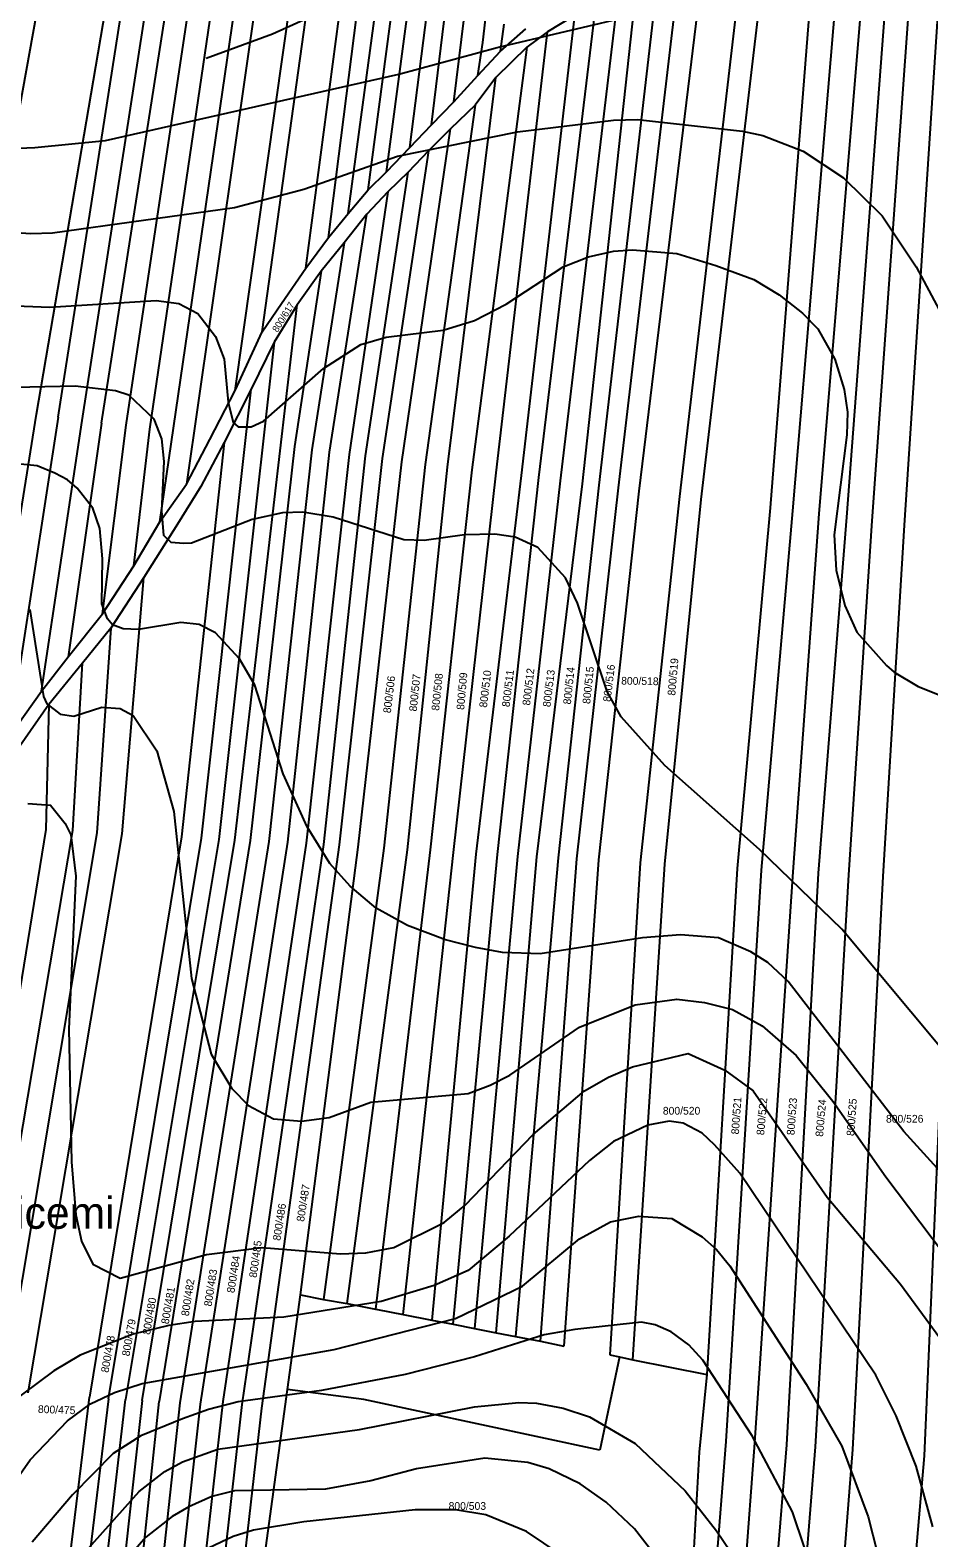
# Model space of a CAD drawing. Extents: x -555860 to -552701, y -1187050 to -1182291.
# Drawn here: x -555051.8 to -554854.6, y -1186105 to -1185774.2 of the extents above; entities that cross this region are included whole.
import ezdxf

# ---------------------------------------------------------------- set-up
doc = ezdxf.new("R2010")
doc.units = 0
for name, color, linetype in [('LEG_2b', 7, 'Continuous'), ('Level 40', 7, 'Continuous'), ('Level 41', 7, 'Continuous'), ('Level 42', 7, 'Continuous'), ('navrh_BV', 7, 'Continuous'), ('Parcelní čísla', 7, 'Continuous')]:
    doc.layers.add(name, color=color, linetype=linetype)

msp = doc.modelspace()

# ---------------------------------------------------------------- linework, layer by layer
at = {"layer": 'Level 40'}
for points in [[(-555084.64, -1185816.58), (-555051.64, -1185818.8), (-555046.92, -1185818.66), (-555006.99, -1185813.11), (-554991.74, -1185809.09), (-554971.22, -1185801.88), (-554944.87, -1185796.48), (-554923.8, -1185793.98), (-554918.53, -1185793.84), (-554895.51, -1185796.34), (-554891.07, -1185797.31), (-554882.2, -1185800.77), (-554873.32, -1185806.6), (-554864.87, -1185814.92), (-554857.38, -1185826.15), (-554846.7, -1185846.11)], [(-555052.33, -1185943.87), (-555047.34, -1185944.28), (-555044.15, -1185948.3), (-555042.9, -1185950.8), (-555041.79, -1185959.81), (-555043.32, -1185993.37), (-555042.76, -1186022.49), (-555041.79, -1186034.13), (-555040.55, -1186039.96), (-555038.05, -1186044.95), (-555032.03, -1186048.01), (-555013.09, -1186042.87), (-555000.89, -1186041.34), (-554983.7, -1186042.73), (-554978.15, -1186042.45), (-554972.05, -1186041.34), (-554960.96, -1186035.8), (-554956.38, -1186032.05), (-554941.41, -1186016.52), (-554930.18, -1186006.96), (-554924.91, -1186003.91), (-554919.64, -1186001.69), (-554907.44, -1185998.78), (-554899.39, -1186002.38), (-554893.15, -1186006.96), (-554876.93, -1186030.25), (-554860.85, -1186049.39), (-554846.56, -1186068.8)], [(-554911.18, -1186113.45), (-554919.22, -1186103.05), (-554925.46, -1186097.22), (-554931.15, -1186093.2), (-554937.94, -1186089.87), (-554942.65, -1186088.49), (-554952.08, -1186087.52), (-554967.06, -1186089.87), (-554977.04, -1186092.51), (-554987.02, -1186094.31), (-555006.99, -1186094.73), (-555011.98, -1186095.98), (-555016.97, -1186098.19), (-555020.62, -1186100.37), (-555026.4, -1186104.85), (-555064.67, -1186149.22)]]:
    msp.add_lwpolyline(points, dxfattribs=at)
at = {"layer": 'Level 41'}
for points in [[(-555184.61, -1185772.35), (-555182.67, -1185783.16), (-555181.98, -1185798.7), (-555181.14, -1185804.52), (-555179.06, -1185810.34), (-555177.8, -1185811.75), (-555176.84, -1185812.28), (-555175.04, -1185812.56), (-555173.1, -1185812.49), (-555167.28, -1185811.45), (-555148.84, -1185803.27), (-555142.16, -1185801.11), (-555134.56, -1185798.97), (-555125.68, -1185797.72), (-555110.71, -1185797.03), (-555099.61, -1185797.58), (-555084.08, -1185799.53), (-555061.34, -1185800.36), (-555050.81, -1185799.94), (-555035.28, -1185798.42), (-554970.94, -1185783.86), (-554949.31, -1185778.03), (-554902.72, -1185766.94)], [(-555104.05, -1185832.8), (-555047.48, -1185835.02), (-555024.18, -1185833.5), (-555019.19, -1185834.19), (-555015.03, -1185836.41), (-555011.15, -1185841.4), (-555009.21, -1185846.39), (-555008.38, -1185855.82), (-555007.27, -1185860.26), (-555006.16, -1185861.23), (-555003.33, -1185861.25), (-555000.61, -1185859.98), (-554987.44, -1185848.47), (-554979.26, -1185843.2), (-554973.71, -1185841.54), (-554961.23, -1185840.01), (-554954.3, -1185837.94), (-554947.37, -1185834.33), (-554934.89, -1185826.15), (-554929.34, -1185823.93), (-554923.8, -1185822.68), (-554919.64, -1185822.41), (-554909.93, -1185823.24), (-554901.4, -1185825.86), (-554893.02, -1185828.92), (-554887.47, -1185832.25), (-554882.34, -1185836.27), (-554879.01, -1185839.74), (-554875.27, -1185846.39), (-554873.19, -1185853.05), (-554872.49, -1185858.04), (-554872.63, -1185863.03), (-554875.41, -1185884.94), (-554874.99, -1185892.7), (-554873.05, -1185900.47), (-554870.41, -1185906.29), (-554863.9, -1185913.64), (-554862.27, -1185915.1), (-554856.96, -1185918.22), (-554851.97, -1185920.16)], [(-554850.86, -1185998.92), (-554873.74, -1185971.46), (-554891.77, -1185953.99), (-554912.57, -1185935.55), (-554922.13, -1185924.87), (-554925.18, -1185919.33), (-554931.7, -1185899.91), (-554934.33, -1185894.37), (-554940.44, -1185887.71), (-554945.43, -1185885.49), (-554949.86, -1185884.8), (-554956.52, -1185884.94), (-554965.39, -1185886.19), (-554969.83, -1185886.05), (-554985.36, -1185881.06), (-554992.02, -1185879.95), (-554996.45, -1185880.09), (-555003.11, -1185881.61), (-555016.42, -1185886.74), (-555018.17, -1185886.88), (-555020.86, -1185886.6), (-555022.52, -1185885.08), (-555022.94, -1185879.67), (-555022.38, -1185868.85), (-555022.94, -1185863.86), (-555024.6, -1185859.56), (-555030.15, -1185854.3), (-555033.06, -1185853.32), (-555041.93, -1185852.35), (-555061.9, -1185852.77)], [(-554832.42, -1186046.34), (-554860.15, -1186015.83), (-554885.53, -1185982.97), (-554889.96, -1185978.81), (-554893.71, -1185976.45), (-554900.78, -1185973.4), (-554909.1, -1185972.71), (-554917.42, -1185973.4), (-554939.88, -1185976.87), (-554948.2, -1185976.59), (-554954.11, -1185975.49), (-554960.68, -1185973.82), (-554969, -1185970.63), (-554975.93, -1185966.89), (-554981.62, -1185962.03), (-554986.05, -1185957.04), (-554991.05, -1185949), (-554996.31, -1185937.35), (-555002.55, -1185917.94), (-555005.88, -1185912.12), (-555011.15, -1185906.43), (-555014.76, -1185904.63), (-555018.78, -1185904.21), (-555028.07, -1185905.74), (-555031.39, -1185905.6), (-555033.76, -1185904.7), (-555034.86, -1185903.38), (-555036.11, -1185900.05), (-555035.97, -1185890.21), (-555036.52, -1185883.55), (-555038.05, -1185879.11), (-555041.52, -1185874.68), (-555043.6, -1185872.88), (-555046.41, -1185871.4), (-555050.25, -1185869.82), (-555079.37, -1185866.91)], [(-555051.92, -1185901.3), (-555048.86, -1185920.43), (-555048.12, -1185922.03), (-555045.26, -1185924.32), (-555042.21, -1185924.73), (-555036.11, -1185922.79), (-555032.09, -1185923.07), (-555029.18, -1185924.59), (-555024.05, -1185932.36), (-555020.3, -1185945.67), (-555016.42, -1185982.28), (-555012.12, -1185998.92), (-555007.55, -1186006.4), (-555003.94, -1186010.15), (-554998.39, -1186013.06), (-554992.29, -1186013.61), (-554986.19, -1186012.78), (-554977.04, -1186009.45), (-554955.69, -1186007.51), (-554950.89, -1186005.69), (-554946.54, -1186003.49), (-554931.28, -1185992.95), (-554919.08, -1185988.1), (-554909.93, -1185986.85), (-554903.83, -1185987.54), (-554897.73, -1185989.07), (-554891.21, -1185992.68), (-554883.72, -1185999.19), (-554875.68, -1186009.18), (-554864.04, -1186025.81), (-554846.43, -1186049.11)], [(-554853.77, -1186102.63), (-554857.38, -1186089.32), (-554861.82, -1186078.23), (-554866.25, -1186069.35), (-554896.07, -1186024.98), (-554901.63, -1186018.8), (-554904.38, -1186016.25), (-554908.54, -1186014.03), (-554911.59, -1186013.61), (-554916.31, -1186014.44), (-554923.8, -1186018.05), (-554929.07, -1186022.21), (-554946.68, -1186038.85), (-554955.69, -1186046.34), (-554963.18, -1186049.66), (-554974.82, -1186053.13), (-554996.18, -1186056.6), (-555015.59, -1186057.57), (-555021.41, -1186058.4), (-555029.18, -1186060.34), (-555040.82, -1186064.92), (-555046.65, -1186068.38), (-555060.73, -1186078.84)], [(-555068.69, -1186114.55), (-555061.2, -1186101.24), (-555051.78, -1186087.93), (-555043.6, -1186079.34), (-555038.6, -1186075.59), (-555033.34, -1186073.1), (-555027.23, -1186071.16), (-554985.08, -1186063.67), (-554958.46, -1186056.87), (-554943.76, -1186049.8), (-554931.28, -1186039.4), (-554924.49, -1186035.66), (-554918.25, -1186034.41), (-554911.04, -1186034.97), (-554904.39, -1186038.99), (-554901.2, -1186041.76), (-554898.28, -1186045.36), (-554881.51, -1186071.29), (-554873.74, -1186084.88), (-554867.92, -1186100.41), (-554865.98, -1186108.18)], [(-554876.79, -1186122.32), (-554884.56, -1186099.3), (-554893.43, -1186082.66), (-554904.25, -1186066.03), (-554907.3, -1186062.7), (-554911.18, -1186059.79), (-554914.65, -1186058.26), (-554917.7, -1186057.71), (-554932.3, -1186059.28), (-554939.05, -1186060.48), (-554954.3, -1186065.33), (-554969.55, -1186069.21), (-554987.86, -1186072.68), (-555006.16, -1186075.18), (-555012.7, -1186076.86), (-555018.36, -1186078.92), (-555027.51, -1186082.66), (-555033.61, -1186086.55), (-555042.49, -1186095.56), (-555051.36, -1186105.96)], [(-555046.23, -1186115.39), (-555027.93, -1186094.87), (-555022.24, -1186090.43), (-555018.36, -1186088.35), (-555010.6, -1186085.58), (-554979.54, -1186081.28), (-554954.3, -1186076.29), (-554944.59, -1186075.31), (-554940.71, -1186075.45), (-554934.89, -1186076.56), (-554929.07, -1186078.5), (-554919.08, -1186084.33), (-554908.13, -1186094.73), (-554901.2, -1186103.46), (-554895.23, -1186112.34)], [(-554935.31, -1186108.73), (-554942.93, -1186103.6), (-554951.81, -1186100), (-554958.46, -1186098.89), (-554967.33, -1186098.89), (-554991.74, -1186101.52), (-555002.83, -1186103.32), (-555007.27, -1186104.71), (-555013.92, -1186107.9)]]:
    msp.add_lwpolyline(points, dxfattribs=at)
at = {"layer": 'Level 42'}
msp.add_lwpolyline([(-554983.42, -1185768.19), (-554998.67, -1185775.12), (-555013.23, -1185780.39)], dxfattribs=at)
at = {"layer": 'navrh_BV'}
for p, q in [((-554982.02, -1185814.46), (-554959.92, -1185649.54)), ((-554977.67, -1185809.26), (-554956.6, -1185649.98)), ((-554973.61, -1185805.31), (-554953.22, -1185650.45)), ((-554968.51, -1185799.97), (-554949.64, -1185650.97)), ((-554963.75, -1185794.98), (-554946.21, -1185651.35)), ((-554958.83, -1185789.9), (-554942.03, -1185651.95)), ((-554952.52, -1185776.9), (-554937.49, -1185652.47)), ((-554859.96, -1185882.85), (-554849.45, -1185721.76)), ((-554855.98, -1185726.5), (-554867.12, -1185881.84)), ((-554872.62, -1185881.1), (-554861.23, -1185730.31)), ((-554866.67, -1185734.17), (-554878.75, -1185880.35)), ((-554884.47, -1185879.66), (-554872.53, -1185738.34)), ((-554878.7, -1185742.52), (-554889.44, -1185879.02)), ((-555065.93, -1185856.6), (-555046.39, -1185748.29)), ((-555050.39, -1185858.49), (-555031.9, -1185750.08)), ((-555045.67, -1185859.13), (-555028.65, -1185750.2)), ((-555040.38, -1185859.85), (-555023.51, -1185750.69)), ((-555036.13, -1185860.41), (-555019.06, -1185751.1)), ((-555030.76, -1185860.91), (-555014.38, -1185751.72)), ((-555025.53, -1185861.73), (-555009.48, -1185752.08)), ((-554904.61, -1185877.17), (-554889.53, -1185749.24)), ((-555023.38, -1185882.09), (-555004.52, -1185752.72)), ((-555000.25, -1185753.32), (-555017.54, -1185873.81)), ((-555006.82, -1185853.26), (-554992.76, -1185754.15)), ((-555000.88, -1185840.42), (-554989, -1185754.53)), ((-554991.36, -1185826.46), (-554981.97, -1185755.45)), ((-554894.9, -1185752.64), (-554909.31, -1185876.55)), ((-554986.36, -1185819.67), (-554978.29, -1185755.97)), ((-554903.84, -1185757.33), (-554918.26, -1185875.33)), ((-554914.11, -1185762.35), (-554927.02, -1185874.08)), ((-554922.74, -1185874.61), (-554909.18, -1185760.02)), ((-554930.6, -1185873.72), (-554918.75, -1185764.53)), ((-554940.2, -1185872.39), (-554927.65, -1185768.32)), ((-554922.78, -1185766.24), (-554935.49, -1185873.07)), ((-554932.38, -1185771), (-554944.07, -1185871.91)), ((-554932.38, -1185771), (-554938.32, -1185774.55)), ((-554949.55, -1185871.34), (-554938.32, -1185774.55)), ((-554948.58, -1185778.8), (-554947.83, -1185772.9)), ((-554948.58, -1185778.8), (-554943.07, -1185773.89)), ((-554938.32, -1185774.55), (-554942.87, -1185777.91)), ((-554942.87, -1185777.91), (-554954.9, -1185870.71)), ((-554953.58, -1185784.12), (-554952.52, -1185776.9)), ((-554953.58, -1185784.12), (-554948.58, -1185778.8)), ((-554942.87, -1185777.91), (-554949.62, -1185784.57)), ((-554960.21, -1185870.12), (-554949.62, -1185784.57)), ((-554958.83, -1185789.9), (-554953.58, -1185784.12)), ((-554949.62, -1185784.57), (-554954.2, -1185790.65)), ((-554954.2, -1185790.65), (-554965.11, -1185869.54)), ((-554963.75, -1185794.98), (-554958.83, -1185789.9)), ((-554954.2, -1185790.65), (-554959.61, -1185795.84)), ((-554968.51, -1185799.97), (-554963.75, -1185794.98)), ((-554970.23, -1185868.95), (-554959.61, -1185795.84)), ((-554959.61, -1185795.84), (-554964.42, -1185800.72)), ((-554964.42, -1185800.72), (-554974.57, -1185868.21)), ((-554973.61, -1185805.31), (-554968.51, -1185799.97)), ((-554964.42, -1185800.72), (-554968.89, -1185805.34)), ((-554978.25, -1185867.62), (-554968.89, -1185805.34)), ((-554977.67, -1185809.26), (-554973.61, -1185805.31)), ((-554968.89, -1185805.34), (-554973.31, -1185809.67)), ((-554982.02, -1185814.46), (-554977.67, -1185809.26)), ((-554973.31, -1185809.67), (-554981.79, -1185867.31)), ((-554973.31, -1185809.67), (-554977.94, -1185814.61)), ((-554986.36, -1185819.67), (-554982.02, -1185814.46)), ((-554986.15, -1185866.78), (-554977.94, -1185814.61)), ((-554977.94, -1185814.61), (-554982.94, -1185820.84)), ((-554991.36, -1185826.46), (-554986.36, -1185819.67)), ((-554982.94, -1185820.84), (-554989.99, -1185866.27)), ((-554982.94, -1185820.84), (-554987.94, -1185827.08)), ((-554996.7, -1185834.21), (-554991.36, -1185826.46)), ((-554987.94, -1185827.08), (-554993.84, -1185865.57)), ((-554987.94, -1185827.08), (-554993.2, -1185834.5)), ((-555006.92, -1185951.95), (-554993.2, -1185834.5)), ((-555000.88, -1185840.42), (-554996.7, -1185834.21)), ((-554993.2, -1185834.5), (-554998.31, -1185842.65)), ((-555006.82, -1185853.26), (-555000.88, -1185840.42)), ((-554998.31, -1185842.65), (-555010.4, -1185951.81)), ((-554998.31, -1185842.65), (-555003.33, -1185852.98)), ((-555014.23, -1185951.48), (-555003.33, -1185852.98)), ((-555012.37, -1185863.99), (-555006.82, -1185853.26)), ((-555003.33, -1185852.98), (-555009.23, -1185864.67)), ((-555063.31, -1185938.92), (-555050.39, -1185858.49)), ((-555045.67, -1185859.13), (-555056.48, -1185929.31)), ((-555049.33, -1185919.22), (-555040.38, -1185859.85)), ((-555036.13, -1185860.41), (-555043.44, -1185911.74)), ((-555035.91, -1185902.24), (-555030.76, -1185860.91)), ((-555029.06, -1185891.72), (-555025.53, -1185861.73)), ((-555009.23, -1185864.67), (-555018.58, -1185951.19)), ((-555017.54, -1185873.81), (-555012.37, -1185863.99)), ((-555009.23, -1185864.67), (-555014.36, -1185874.35)), ((-554993.84, -1185865.57), (-555003.52, -1185952.03)), ((-554989.99, -1185866.27), (-554999.42, -1185952.21)), ((-554995.31, -1185952.4), (-554986.15, -1185866.78)), ((-554981.79, -1185867.31), (-554991.22, -1185952.61)), ((-554987.4, -1185952.88), (-554978.25, -1185867.62)), ((-554974.57, -1185868.21), (-554983.98, -1185952.99)), ((-554979.84, -1185953.45), (-554970.23, -1185868.95)), ((-554965.11, -1185869.54), (-554974.19, -1185953.69)), ((-554969.03, -1185954.07), (-554960.21, -1185870.12)), ((-554954.9, -1185870.71), (-554964.02, -1185954.09)), ((-554958.93, -1185954.61), (-554949.55, -1185871.34)), ((-555023.38, -1185882.09), (-555017.54, -1185873.81)), ((-555014.36, -1185874.35), (-555019.51, -1185882.61)), ((-554944.07, -1185871.91), (-554954.05, -1185955.03)), ((-554949.26, -1185955.11), (-554940.2, -1185872.39)), ((-554935.49, -1185873.07), (-554944.86, -1185955.52)), ((-554940.64, -1185955.6), (-554930.6, -1185873.72)), ((-554927.02, -1185874.08), (-554935.99, -1185955.84)), ((-554931.88, -1185956.02), (-554922.74, -1185874.61)), ((-554918.26, -1185875.33), (-554927.13, -1185956.28)), ((-554909.31, -1185876.55), (-554917.99, -1185956.91)), ((-554912.58, -1185957.17), (-554904.61, -1185877.17)), ((-554889.44, -1185879.02), (-554896.7, -1185958.17)), ((-554891.31, -1185958.54), (-554884.47, -1185879.66)), ((-554878.75, -1185880.35), (-554884.5, -1185958.89)), ((-554878.85, -1185959.18), (-554872.62, -1185881.1)), ((-555029.06, -1185891.72), (-555023.38, -1185882.09)), ((-555019.51, -1185882.61), (-555026.88, -1185894.33)), ((-554867.12, -1185881.84), (-554872.24, -1185959.56)), ((-554864.65, -1185959.94), (-554859.96, -1185882.85)), ((-555035.91, -1185902.24), (-555029.06, -1185891.72)), ((-555026.88, -1185894.33), (-555034.1, -1185905.44)), ((-555031.59, -1185950.56), (-555026.88, -1185894.33)), ((-555043.44, -1185911.74), (-555035.91, -1185902.24)), ((-555034.1, -1185905.44), (-555040.31, -1185913.08)), ((-555034.1, -1185905.44), (-555037.18, -1185950.35)), ((-555049.33, -1185919.22), (-555043.44, -1185911.74)), ((-555040.31, -1185913.08), (-555047.71, -1185922.2)), ((-555042.48, -1185949.81), (-555040.31, -1185913.08)), ((-555056.48, -1185929.31), (-555049.33, -1185919.22)), ((-555047.71, -1185922.2), (-555054.07, -1185931.3)), ((-555047.71, -1185922.2), (-555048.34, -1185949.57)), ((-555048.34, -1185949.57), (-555068.31, -1186072.02)), ((-555063.2, -1186072.55), (-555042.48, -1185949.81)), ((-555037.18, -1185950.35), (-555057.66, -1186072.82)), ((-555052.27, -1186073.22), (-555031.59, -1185950.56)), ((-555018.58, -1185951.19), (-555038.82, -1186074.15)), ((-555034.62, -1186074.53), (-555014.23, -1185951.48)), ((-555010.4, -1185951.81), (-555030.91, -1186074.64)), ((-555027.23, -1186074.92), (-555006.92, -1185951.95)), ((-555003.52, -1185952.03), (-555023.48, -1186075.09)), ((-554999.42, -1185952.21), (-555018.96, -1186075.4)), ((-555014.44, -1186075.72), (-554995.31, -1185952.4)), ((-554991.22, -1185952.61), (-555009.55, -1186075.13)), ((-555005.31, -1186075.79), (-554987.4, -1185952.88)), ((-554983.98, -1185952.99), (-555001.03, -1186076.57)), ((-554992.51, -1186051.73), (-554979.84, -1185953.45)), ((-554974.19, -1185953.69), (-554987.43, -1186052.7)), ((-554982.27, -1186053.6), (-554969.03, -1185954.07)), ((-554964.02, -1185954.09), (-554976.04, -1186054.81)), ((-554969.98, -1186056.05), (-554958.93, -1185954.61)), ((-554954.05, -1185955.03), (-554963.67, -1186057.25)), ((-554959.01, -1186058.11), (-554949.26, -1185955.11)), ((-554944.86, -1185955.52), (-554954.29, -1186059.1)), ((-554949.55, -1186060.07), (-554940.64, -1185955.6)), ((-554935.99, -1185955.84), (-554945.3, -1186060.84)), ((-554939.86, -1186061.89), (-554931.88, -1185956.02)), ((-554927.13, -1185956.28), (-554934.69, -1186062.95)), ((-554917.99, -1185956.91), (-554924.66, -1186064.86)), ((-554919.58, -1186065.93), (-554912.58, -1185957.17)), ((-554896.7, -1185958.17), (-554903.31, -1186069.17)), ((-554899.07, -1186083.85), (-554891.31, -1185958.54)), ((-554884.5, -1185958.89), (-554892.88, -1186084.16)), ((-554885.79, -1186084.58), (-554878.85, -1185959.18)), ((-554872.24, -1185959.56), (-554879.59, -1186085.08)), ((-554871.31, -1186085.63), (-554864.65, -1185959.94)), ((-554855.59, -1186087.02), (-554850.1, -1185960.76)), ((-554995.34, -1186072.49), (-554992.51, -1186051.73)), ((-554992.51, -1186051.73), (-554987.43, -1186052.7)), ((-554987.43, -1186052.7), (-554982.27, -1186053.6)), ((-554982.27, -1186053.6), (-554976.04, -1186054.81)), ((-554976.04, -1186054.81), (-554975.63, -1186054.9)), ((-554975.63, -1186054.9), (-554969.98, -1186056.05)), ((-554969.98, -1186056.05), (-554963.67, -1186057.25)), ((-554963.67, -1186057.25), (-554959.01, -1186058.11)), ((-554959.01, -1186058.11), (-554954.29, -1186059.1)), ((-554954.29, -1186059.1), (-554949.55, -1186060.07)), ((-554949.55, -1186060.07), (-554945.3, -1186060.84)), ((-554945.3, -1186060.84), (-554939.86, -1186061.89)), ((-554939.86, -1186061.89), (-554934.69, -1186062.95)), ((-554922.5, -1186065.32), (-554926.83, -1186085.78)), ((-554924.66, -1186064.86), (-554922.5, -1186065.32)), ((-554922.5, -1186065.32), (-554919.58, -1186065.93)), ((-554919.58, -1186065.93), (-554903.31, -1186069.17)), ((-554903.31, -1186069.17), (-554905, -1186086.24)), ((-555000.73, -1186112.03), (-554995.34, -1186072.49)), ((-554978.61, -1186074.64), (-554995.34, -1186072.49)), ((-555050.26, -1186168.24), (-555038.82, -1186074.15)), ((-555034.62, -1186074.53), (-555046.03, -1186168.83)), ((-555041.95, -1186169.53), (-555030.91, -1186074.64)), ((-555027.23, -1186074.92), (-555037.87, -1186170.22)), ((-555033.7, -1186170.75), (-555023.48, -1186075.09)), ((-555018.96, -1186075.4), (-555029.4, -1186171.48)), ((-555025.1, -1186172.2), (-555014.44, -1186075.72)), ((-555009.55, -1186075.13), (-555020.66, -1186172.94)), ((-555016.34, -1186173.62), (-555005.31, -1186075.79)), ((-555001.03, -1186076.57), (-555012.25, -1186174.29)), ((-554926.83, -1186085.78), (-554978.61, -1186074.64)), ((-554913.63, -1186264.75), (-554899.07, -1186083.85)), ((-554905, -1186086.24), (-554907.51, -1186131.03)), ((-554892.88, -1186084.16), (-554906.34, -1186263.88)), ((-554900.36, -1186263.12), (-554885.79, -1186084.58)), ((-554879.59, -1186085.08), (-554893.59, -1186261.84)), ((-554885.02, -1186259.59), (-554871.31, -1186085.63)), ((-554869.97, -1186255.68), (-554855.59, -1186087.02))]:
    msp.add_line(p, q, dxfattribs=at)

# ---------------------------------------------------------------- texts
at = {"layer": 'LEG_2b'}
for s, height, rotation, p in [('800/617', 1.5, 58, (-554997.55, -1185840.62)), ('800/512', 1.7, 83, (-554942.15, -1185922.47)), ('800/513', 1.7, 83, (-554937.67, -1185922.81)), ('800/514', 1.7, 84, (-554933.19, -1185922.23)), ('800/515', 1.7, 84, (-554928.95, -1185922.11)), ('800/516', 1.7, 83, (-554924.47, -1185921.66)), ('800/519', 1.7, 85, (-554910.28, -1185920.27)), ('800/506', 1.7, 83, (-554972.7, -1185924.15)), ('800/507', 1.7, 84, (-554967, -1185923.77)), ('800/508', 1.7, 84, (-554962.09, -1185923.59)), ('800/509', 1.7, 85, (-554956.59, -1185923.41)), ('800/510', 1.7, 83, (-554951.61, -1185922.93)), ('800/511', 1.7, 83, (-554946.63, -1185922.81)), ('800/518', 1.7, 359, (-554922.15, -1185917.8)), ('800/521', 1.7, 86, (-554896.31, -1186016.55)), ('800/522', 1.7, 85, (-554890.77, -1186016.73)), ('800/523', 1.7, 86, (-554884.12, -1186016.72)), ('800/524', 1.7, 85, (-554877.84, -1186017.07)), ('800/525', 1.7, 86, (-554871, -1186016.89)), ('800/487', 1.7, 81, (-554991.72, -1186035.74)), ('800/486', 1.7, 81, (-554996.92, -1186039.91)), ('800/485', 1.7, 82, (-555002.12, -1186048.04)), ('800/484', 1.7, 81, (-555007.02, -1186051.39)), ('800/483', 1.7, 81, (-555012.02, -1186054.35)), ('800/481', 1.7, 80, (-555021.43, -1186058.24)), ('800/482', 1.7, 81, (-555017.02, -1186056.48)), ('800/480', 1.7, 80, (-555025.53, -1186060.55)), ('800/479', 1.7, 80, (-555030.03, -1186065.27)), ('800/478', 1.7, 80, (-555034.63, -1186068.88)), ('800/475', 1.7, 358, (-555050.13, -1186077.61))]:
    msp.add_text(s, height=height, rotation=rotation, dxfattribs=at).set_placement(p)
for s, p in [('800/520', (-554912.99, -1186012.16)), ('800/526', (-554864.03, -1186013.92)), ('800/503', (-554960, -1186098.88))]:
    msp.add_text(s, height=1.7, dxfattribs=at).set_placement(p)
at = {"layer": 'Parcelní čísla'}
msp.add_text('Za zelnicemi', height=7, dxfattribs=at).set_placement((-555085.82, -1186037.21))

doc.saveas('drawing.dxf')
